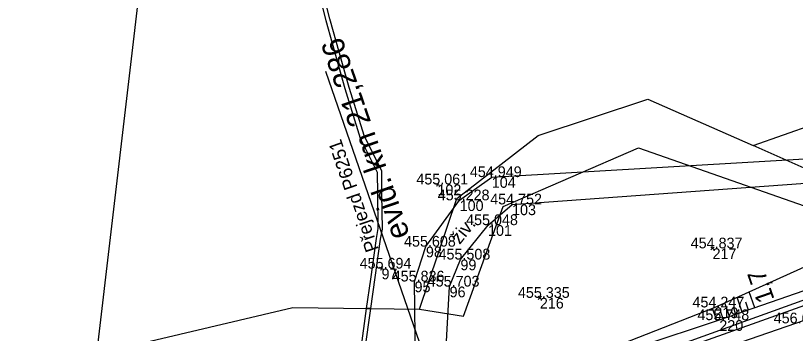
# Model space of a CAD drawing. Extents: x -776734 to -748832, y -1118122 to -976986.
# Drawn here: x -750954.7 to -750867.4, y -1114593.7 to -1114558 of the extents above; entities that cross this region are included whole.
import ezdxf

# ---------------------------------------------------------------- set-up
doc = ezdxf.new("R2010")
doc.units = 0
for name, color, linetype in [('KM_Hranice parcel', 7, 'Continuous'), ('KM_Věcná břemena k části', 7, 'Continuous'), ('OSA', 7, 'Continuous'), ('SŽG Vrstva 1', 7, 'Continuous'), ('SŽG Vrstva 4', 7, 'Continuous'), ('SŽG Vrstva 48', 7, 'Continuous'), ('SŽG Vrstva 49', 7, 'Continuous'), ('SŽG Vrstva 51', 7, 'Continuous'), ('SŽG Vrstva 53', 7, 'Continuous'), ('SŽG Vrstva 60', 7, 'Continuous'), ('SŽG Vrstva 61', 7, 'Continuous')]:
    doc.layers.add(name, color=color, linetype=linetype)

msp = doc.modelspace()

# ---------------------------------------------------------------- linework, layer by layer
at = {"layer": 'KM_Hranice parcel'}
msp.add_line((-750872.08, -1114572.6), (-750784.54, -1114541.68), dxfattribs=at)
for points in [[(-751154.53, -1114472.31), (-751147.55, -1114479.1), (-751148.65, -1114481.83), (-751152.49, -1114497.62), (-751130.98, -1114497.11), (-751108.06, -1114492.36), (-751077.89, -1114489.91), (-751077.75, -1114475.44), (-751018.04, -1114477.32), (-750975.93, -1114483.83), (-750935.34, -1114508.17), (-750945.62, -1114595.97)], [(-750784.54, -1114541.68), (-750789.31, -1114548.64), (-750856.37, -1114575.86), (-750864.03, -1114576.18), (-750872.08, -1114572.6)], [(-750909.46, -1114590.94), (-750904.52, -1114591.74), (-750900.07, -1114579.45), (-750884.93, -1114572.87), (-750860.41, -1114581.47), (-750789.41, -1114554.45)], [(-750909.46, -1114590.94), (-750905.29, -1114578.54), (-750896.15, -1114571.47), (-750883.9, -1114567.43), (-750872.08, -1114572.6)], [(-750945.62, -1114595.97), (-750923.65, -1114590.78), (-750909.46, -1114590.94)]]:
    msp.add_lwpolyline(points, dxfattribs=at)
at = {"layer": 'KM_Věcná břemena k části'}
for points in [[(-750914.42, -1114587.4), (-750913.82, -1114583.11), (-750913.61, -1114581.97), (-750913.67, -1114578.02), (-750913.68, -1114575.46), (-750915.62, -1114571.58), (-750917.33, -1114566.1), (-750919.49, -1114558.42), (-750921.55, -1114550.29), (-750923.83, -1114541.21), (-750925.69, -1114533.3), (-750927.84, -1114525.79), (-750929.91, -1114518.66), (-750932.14, -1114512.85), (-750935.21, -1114507.42), (-750939.04, -1114503.57), (-750944.34, -1114498.37), (-750947.68, -1114495.56), (-750950.75, -1114493.87), (-750955.18, -1114491.5)], [(-750935.61, -1114507.73), (-750935.34, -1114508.17), (-750932.59, -1114513.07), (-750930.38, -1114518.81), (-750928.29, -1114526.01), (-750926.18, -1114533.43), (-750924.31, -1114541.33), (-750922.03, -1114550.41), (-750919.96, -1114558.61), (-750917.81, -1114566.23), (-750916.08, -1114571.77), (-750914.18, -1114575.58), (-750914.17, -1114578.03), (-750914.11, -1114581.92), (-750914.32, -1114583.03), (-750914.95, -1114587.6), (-750915.41, -1114590.87), (-750914.91, -1114590.88), (-750914.42, -1114587.4)]]:
    msp.add_lwpolyline(points, dxfattribs=at)
msp.add_lwpolyline([(-750907.53, -1114617.26), (-750905.84, -1114619.22), (-750906.28, -1114617.96), (-750907.13, -1114616.97), (-750909.04, -1114613.78), (-750911.61, -1114609.79), (-750912.46, -1114607.86), (-750913.4, -1114605.78), (-750914.42, -1114602.49), (-750914.59, -1114600.52), (-750915.57, -1114595.61), (-750914.91, -1114590.88), (-750915.41, -1114590.87), (-750916.07, -1114595.63), (-750915.09, -1114600.59), (-750914.92, -1114602.59), (-750913.87, -1114605.95), (-750912.94, -1114608), (-750912.05, -1114610.02), (-750909.47, -1114614.03)], close=True, dxfattribs=at)
at = {"layer": 'OSA'}
msp.add_line((-750860.923, -1114590.3276), (-750912.9148, -1114608.268), dxfattribs=at)
at = {"layer": 'SŽG Vrstva 1'}
msp.add_lwpolyline([(-750820.337, -1114576.326), (-750829.58, -1114579.518), (-750838.838, -1114582.712), (-750848.38, -1114586.005), (-750858.075, -1114589.346), (-750867.336, -1114592.541), (-750876.526, -1114595.715), (-750885.989, -1114598.98), (-750895.385, -1114602.229), (-750902.991, -1114604.843), (-750908.211, -1114606.647), (-750914.742, -1114608.898), (-750924.077, -1114612.114), (-750933.495, -1114615.368), (-750942.896, -1114618.61), (-750952.239, -1114621.829), (-750961.799, -1114625.127)], dxfattribs=at)
at = {"layer": 'SŽG Vrstva 4'}
msp.add_line((-750905.6182, -1114605.751), (-750919.9433, -1114564.3003), dxfattribs=at)
for points in [[(-750824.673, -1114575.386), (-750842.852, -1114581.727), (-750861.561, -1114588.189), (-750880.945, -1114595.155), (-750899.361, -1114601.468), (-750902.908, -1114603.401)], [(-750824.563, -1114575.932), (-750842.715, -1114582.202), (-750861.411, -1114588.769), (-750880.904, -1114595.722), (-750899.175, -1114602.016), (-750902.908, -1114603.401)]]:
    msp.add_lwpolyline(points, dxfattribs=at)
at = {"layer": 'SŽG Vrstva 48'}
for p, q in [((-750873.313, -1114591.294), (-750873.896, -1114589.614)), ((-750871.896, -1114590.803), (-750872.523, -1114588.994)), ((-750874.731, -1114591.785), (-750875.268, -1114590.234)), ((-750872.605, -1114591.048), (-750872.907, -1114590.176)), ((-750876.149, -1114592.272), (-750876.626, -1114590.835)), ((-750875.439, -1114592.03), (-750875.697, -1114591.287)), ((-750874.022, -1114591.539), (-750874.302, -1114590.731))]:
    msp.add_line(p, q, dxfattribs=at)
at = {"layer": 'SŽG Vrstva 49'}
for p, q in [((-750907.2224, -1114577.0837), (-750907.6716, -1114576.8643)), ((-750907.3373, -1114576.7494), (-750907.5567, -1114577.1986)), ((-750876.8088, -1114584.3128), (-750876.4552, -1114583.9592)), ((-750876.4552, -1114584.3128), (-750876.8088, -1114583.9592)), ((-750913.4822, -1114586.5103), (-750913.9318, -1114586.2917)), ((-750913.5977, -1114586.1762), (-750913.8163, -1114586.6258)), ((-750896.1508, -1114589.8598), (-750895.7972, -1114589.5062)), ((-750895.7972, -1114589.8598), (-750896.1508, -1114589.5062))]:
    msp.add_line(p, q, dxfattribs=at)
for points in [[(-750902.869, -1114601.131), (-750876.43, -1114590.758), (-750847.082, -1114577.508), (-750846.11, -1114576.392), (-750828.341, -1114569.281)], [(-750829.333, -1114576.055), (-750875.877, -1114592.182), (-750902.869, -1114601.131)]]:
    msp.add_lwpolyline(points, dxfattribs=at)
at = {"layer": 'SŽG Vrstva 51'}
for points in [[(-750907.847, -1114605.676), (-750909.898, -1114596.967), (-750910.005, -1114587.848), (-750908.734, -1114583.94), (-750904.958, -1114578.749), (-750901.36, -1114576.145), (-750861.222, -1114573.82)], [(-750907.847, -1114605.676), (-750904.542, -1114604.506), (-750906.55, -1114596.602), (-750906.082, -1114588.417), (-750904.868, -1114585.385), (-750901.781, -1114581.531), (-750899.088, -1114579.21), (-750860.591, -1114576.435)]]:
    msp.add_lwpolyline(points, dxfattribs=at)
at = {"layer": 'SŽG Vrstva 53'}
msp.add_lwpolyline([(-751091.59, -1114651.24), (-751052.09, -1114634.98), (-750945.62, -1114595.97), (-750923.65, -1114590.78), (-750909.46, -1114590.94), (-750904.52, -1114591.74), (-750900.07, -1114579.45), (-750884.93, -1114572.87), (-750860.41, -1114581.47), (-750789.41, -1114554.45)], dxfattribs=at)
at = {"layer": 'SŽG Vrstva 60'}
for p, q in [((-750901.36, -1114576.145), (-750901.36, -1114576.145)), ((-750907.447, -1114576.974), (-750907.447, -1114576.974)), ((-750904.958, -1114578.749), (-750904.958, -1114578.749)), ((-750899.088, -1114579.21), (-750899.088, -1114579.21)), ((-750901.781, -1114581.531), (-750901.781, -1114581.531)), ((-750908.734, -1114583.94), (-750908.734, -1114583.94)), ((-750876.632, -1114584.136), (-750876.632, -1114584.136)), ((-750904.868, -1114585.385), (-750904.868, -1114585.385)), ((-750913.707, -1114586.401), (-750913.707, -1114586.401)), ((-750910.005, -1114587.848), (-750910.005, -1114587.848)), ((-750906.082, -1114588.417), (-750906.082, -1114588.417)), ((-750895.974, -1114589.683), (-750895.974, -1114589.683)), ((-750876.43, -1114590.758), (-750876.43, -1114590.758)), ((-750875.877, -1114592.182), (-750875.877, -1114592.182))]:
    msp.add_line(p, q, dxfattribs=at)

# ---------------------------------------------------------------- texts
at = {"layer": 'SŽG Vrstva 4'}
for s, height, rotation, p in [('evid. km 21,286', 2.5, 108.966618, (-750910.511, -1114582.6414)), ('Přejezd P6251', 1.5, 108.945759, (-750913.9971, -1114584.2399))]:
    msp.add_text(s, height=height, rotation=rotation, dxfattribs=at).set_placement(p)
at = {"layer": 'SŽG Vrstva 48'}
msp.add_text('1,7', height=2, rotation=109.110656, dxfattribs=at).set_placement((-750869.679, -1114589.826))
at = {"layer": 'SŽG Vrstva 51'}
msp.add_text('živ.', height=1.5, rotation=51.305761, dxfattribs=at).set_placement((-750904.9465, -1114583.7681))
at = {"layer": 'SŽG Vrstva 60'}
for s, p in [('104', (-750901.36, -1114577.345)), ('102', (-750907.447, -1114578.174)), ('100', (-750904.958, -1114579.949)), ('103', (-750899.088, -1114580.41)), ('101', (-750901.781, -1114582.731)), ('98', (-750908.734, -1114585.14)), ('217', (-750876.632, -1114585.336)), ('99', (-750904.868, -1114586.585)), ('97', (-750913.707, -1114587.601)), ('95', (-750910.005, -1114589.048)), ('96', (-750906.082, -1114589.617)), ('216', (-750895.974, -1114590.883)), ('219', (-750876.43, -1114591.958)), ('220', (-750875.877, -1114593.382))]:
    msp.add_text(s, height=1.2, dxfattribs=at).set_placement(p)
at = {"layer": 'SŽG Vrstva 61'}
for s, p in [('454.949', (-750903.8137, -1114576.145)), ('455.061', (-750909.8044, -1114576.974)), ('455.228', (-750907.4117, -1114578.749)), ('454.752', (-750901.5362, -1114579.21)), ('455.048', (-750904.2347, -1114581.531)), ('455.608', (-750911.1877, -1114583.94)), ('454.837', (-750879.0839, -1114584.136)), ('455.508', (-750907.3217, -1114585.385)), ('455.694', (-750916.158, -1114586.401)), ('455.836', (-750912.4569, -1114587.848)), ('455.703', (-750908.5339, -1114588.417)), ('455.335', (-750898.4301, -1114589.683)), ('454.247', (-750878.8819, -1114590.758)), ('455.748', (-750878.3307, -1114592.182)), ('456.656', (-750869.7879, -1114592.541))]:
    msp.add_text(s, height=1.2, dxfattribs=at).set_placement(p)

doc.saveas('drawing.dxf')
